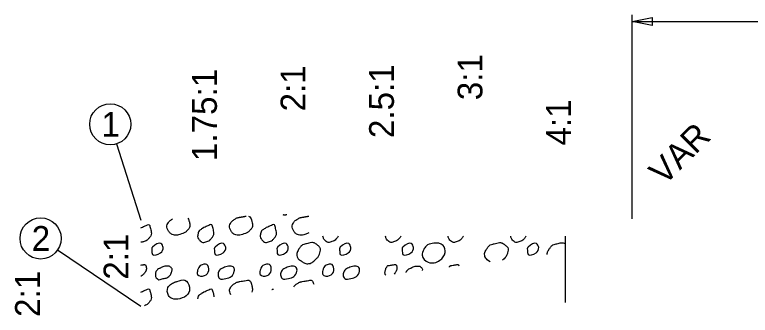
# Model space of a CAD drawing. Extents: x -1577 to 2037, y 0 to 220.
# Drawn here: x 62.87 to 104.42, y 151.65 to 168.62 of the extents above; entities that cross this region are included whole.
import ezdxf

# ---------------------------------------------------------------- set-up
doc = ezdxf.new("R2010")
doc.units = 0
for name, color, linetype in [('DR_P_Culvert', 7, 'Continuous'), ('GE_P_Alignment_100_Stations', 7, 'Continuous'), ('PF_X_Ground_Line', 7, 'Continuous'), ('XS_P_Pavt_Surface', 7, 'Continuous')]:
    doc.layers.add(name, color=color, linetype=linetype)

msp = doc.modelspace()

# ---------------------------------------------------------------- linework, layer by layer
at = {"layer": 'DR_P_Culvert'}
msp.add_line((93.987, 152.378), (93.987, 156.128), dxfattribs=at)
at = {"layer": 'GE_P_Alignment_100_Stations'}
for p, q in [((97.737, 157.091), (97.737, 168.619)), ((97.737, 168.239), (134.487, 168.239)), ((68.615, 161.328), (69.987, 157.031)), ((65.287, 155.341), (69.987, 152.167))]:
    msp.add_line(p, q, dxfattribs=at)
for centre in [(68.262, 162.432), (64.326, 155.99)]:
    msp.add_circle(centre, 1.16, dxfattribs=at)
at = {"layer": 'PF_X_Ground_Line'}
msp.add_lwpolyline([(98.866, 168.011), (97.737, 168.239), (98.866, 168.466)], close=True, dxfattribs=at)
msp.add_lwpolyline([(98.866, 168.011), (97.737, 168.239), (98.866, 168.466)], close=True, dxfattribs=at)
at = {"layer": 'XS_P_Pavt_Surface'}
for points, degree in [([(72.654, 157.128), (72.695, 157.049), (72.722, 156.949), (72.74, 156.879), (72.775, 156.75), (72.753, 156.593), (72.644, 156.473), (72.511, 156.325), (72.362, 156.268), (72.198, 156.22), (72.057, 156.178), (71.899, 156.163), (71.758, 156.223), (71.673, 156.259), (71.611, 156.321), (71.559, 156.401), (71.472, 156.535), (71.447, 156.719), (71.522, 156.846), (71.572, 156.93), (71.64, 157.004), (71.727, 157.059), (71.747, 157.072), (71.767, 157.085), (71.787, 157.097)], 3), ([(76.075, 157.253), (76.187, 157.211), (76.244, 157.002), (76.276, 156.879), (76.311, 156.75), (76.288, 156.593), (76.18, 156.473), (76.046, 156.325), (75.898, 156.268), (75.734, 156.22), (75.593, 156.178), (75.434, 156.163), (75.294, 156.223), (75.208, 156.259), (75.146, 156.321), (75.095, 156.401), (75.008, 156.535), (74.982, 156.719), (75.058, 156.846), (75.108, 156.93), (75.176, 157.004), (75.263, 157.059), (75.337, 157.106), (75.407, 157.15), (75.489, 157.168), (75.516, 157.173), (75.544, 157.179), (75.571, 157.185)], 3), ([(75.563, 157.183), (75.69, 157.205), (75.816, 157.229), (75.943, 157.248)], 2), ([(78.244, 157.332), (78.172, 157.312), (78.097, 157.293), (78.027, 157.324)], 2), ([(79.487, 156.3), (79.418, 156.266), (79.346, 156.242), (79.27, 156.22), (79.128, 156.178), (78.97, 156.163), (78.83, 156.223), (78.744, 156.259), (78.682, 156.321), (78.63, 156.401), (78.544, 156.535), (78.518, 156.719), (78.594, 156.846), (78.644, 156.93), (78.712, 157.004), (78.799, 157.059), (78.872, 157.106), (78.943, 157.15), (79.025, 157.168), (79.052, 157.173), (79.08, 157.179), (79.107, 157.185)], 3), ([(79.099, 157.183), (79.228, 157.206), (79.358, 157.23), (79.487, 157.25)], 2), ([(70.007, 156.601), (70.124, 156.651), (70.242, 156.701), (70.359, 156.752), (70.48, 156.804), (70.54, 156.537), (70.566, 156.413), (70.595, 156.282), (70.561, 156.135), (70.455, 156.008), (70.355, 155.889), (70.241, 155.832), (70.121, 155.796), (70.08, 155.783), (70.034, 155.775), (69.987, 155.778)], 3), ([(73.543, 156.601), (73.66, 156.651), (73.777, 156.701), (73.895, 156.752), (74.016, 156.804), (74.075, 156.537), (74.102, 156.413), (74.13, 156.282), (74.096, 156.135), (73.99, 156.008), (73.891, 155.889), (73.777, 155.832), (73.657, 155.796), (73.561, 155.767), (73.44, 155.762), (73.346, 155.855), (73.233, 155.967), (73.19, 156.1), (73.213, 156.214), (73.231, 156.305), (73.274, 156.425), (73.359, 156.482), (73.42, 156.522), (73.482, 156.561), (73.543, 156.601)], 3), ([(77.079, 156.601), (77.196, 156.651), (77.313, 156.701), (77.43, 156.752), (77.552, 156.804), (77.611, 156.537), (77.638, 156.413), (77.666, 156.282), (77.632, 156.135), (77.526, 156.008), (77.427, 155.889), (77.313, 155.832), (77.193, 155.796), (77.097, 155.767), (76.976, 155.762), (76.882, 155.855), (76.768, 155.967), (76.726, 156.1), (76.749, 156.214), (76.767, 156.305), (76.809, 156.425), (76.895, 156.482), (76.956, 156.522), (77.018, 156.561), (77.079, 156.601)], 3), ([(69.987, 156.588), (69.994, 156.592), (70, 156.597), (70.007, 156.601)], 2), ([(81.139, 156.128), (81.119, 156.087), (81.094, 156.047), (81.062, 156.008), (80.962, 155.889), (80.849, 155.832), (80.729, 155.796), (80.633, 155.767), (80.512, 155.762), (80.418, 155.855), (80.332, 155.94), (80.287, 156.036), (80.28, 156.128)], 3), ([(84.674, 156.128), (84.655, 156.087), (84.63, 156.047), (84.598, 156.008), (84.498, 155.889), (84.384, 155.832), (84.265, 155.796), (84.169, 155.767), (84.048, 155.762), (83.954, 155.855), (83.868, 155.94), (83.823, 156.036), (83.815, 156.128)], 3), ([(88.21, 156.128), (88.191, 156.087), (88.166, 156.047), (88.134, 156.008), (88.034, 155.889), (87.92, 155.832), (87.8, 155.796), (87.704, 155.767), (87.584, 155.762), (87.49, 155.855), (87.404, 155.94), (87.358, 156.036), (87.351, 156.128)], 3), ([(91.746, 156.128), (91.727, 156.087), (91.701, 156.047), (91.67, 156.008), (91.57, 155.889), (91.456, 155.832), (91.336, 155.796), (91.24, 155.767), (91.119, 155.762), (91.025, 155.855), (90.939, 155.94), (90.894, 156.036), (90.887, 156.128)], 3), ([(79.12, 155.632), (79.238, 155.663), (79.357, 155.694), (79.475, 155.725), (79.649, 155.77), (79.823, 155.738), (79.996, 155.593), (80.131, 155.481), (80.139, 155.315), (80.104, 155.191), (80.059, 155.034), (79.96, 154.886), (79.808, 154.756), (79.618, 154.594), (79.354, 154.53), (79.16, 154.645), (79.002, 154.738), (78.836, 154.878), (78.805, 155.043), (78.786, 155.146), (78.84, 155.266), (78.9, 155.362), (78.944, 155.43), (78.982, 155.499), (79.039, 155.554), (79.066, 155.58), (79.093, 155.606), (79.12, 155.632)], 3), ([(89.726, 154.671), (89.582, 154.763), (89.441, 154.893), (89.413, 155.043), (89.394, 155.146), (89.447, 155.266), (89.508, 155.362), (89.551, 155.43), (89.589, 155.499), (89.646, 155.554), (89.673, 155.58), (89.7, 155.606), (89.727, 155.632)], 3), ([(89.727, 155.632), (89.846, 155.663), (89.964, 155.694), (90.083, 155.725), (90.256, 155.77), (90.43, 155.738), (90.604, 155.593), (90.738, 155.481), (90.747, 155.315), (90.711, 155.191), (90.667, 155.035), (90.569, 154.888), (90.418, 154.758)], 3), ([(92.945, 155.079), (92.942, 155.173), (92.99, 155.277), (93.044, 155.362), (93.087, 155.43), (93.125, 155.499), (93.182, 155.554), (93.209, 155.58), (93.236, 155.606), (93.263, 155.632)], 3), ([(93.263, 155.632), (93.381, 155.663), (93.5, 155.694), (93.619, 155.725), (93.741, 155.757), (93.864, 155.75), (93.987, 155.692)], 3), ([(70.94, 154.242), (71.024, 154.284), (71.107, 154.325), (71.19, 154.367), (71.282, 154.413), (71.392, 154.422), (71.491, 154.425), (71.565, 154.427), (71.636, 154.409), (71.702, 154.344), (71.763, 154.284), (71.754, 154.204), (71.736, 154.14), (71.707, 154.035), (71.668, 153.929), (71.565, 153.844), (71.465, 153.761), (71.36, 153.749), (71.252, 153.724), (71.139, 153.697), (71.011, 153.631), (70.9, 153.73), (70.828, 153.795), (70.813, 153.871), (70.815, 153.945), (70.816, 154.012), (70.825, 154.09), (70.866, 154.145), (70.891, 154.178), (70.916, 154.21), (70.94, 154.242)], 3), ([(83.822, 153.922), (83.816, 153.93), (83.81, 153.939), (83.805, 153.949), (83.767, 154.026), (83.786, 154.117), (83.808, 154.195), (83.823, 154.25), (83.83, 154.312), (83.866, 154.358), (83.893, 154.392), (83.92, 154.425), (83.946, 154.459)], 3), ([(83.946, 154.459), (84.074, 154.477), (84.201, 154.497), (84.328, 154.515), (84.442, 154.53), (84.468, 154.285), (84.432, 154.186), (84.406, 154.115), (84.355, 154.044), (84.294, 153.982)], 3), ([(84.973, 154.068), (84.981, 154.096), (84.992, 154.123), (85.01, 154.145), (85.034, 154.178), (85.059, 154.21), (85.084, 154.242)], 3), ([(85.084, 154.242), (85.167, 154.284), (85.25, 154.325), (85.334, 154.367), (85.425, 154.413), (85.535, 154.422), (85.635, 154.425), (85.708, 154.427), (85.779, 154.409), (85.845, 154.344), (85.893, 154.297), (85.898, 154.238), (85.889, 154.184)], 3), ([(87.418, 154.378), (87.439, 154.405), (87.461, 154.432), (87.482, 154.459)], 2), ([(87.482, 154.459), (87.609, 154.477), (87.737, 154.497), (87.864, 154.515), (87.906, 154.52), (87.935, 154.491), (87.955, 154.446)], 3), ([(75.07, 152.812), (75.004, 152.941), (74.99, 153.102), (75.058, 153.215), (75.108, 153.299), (75.176, 153.373), (75.263, 153.429), (75.337, 153.476), (75.407, 153.52), (75.489, 153.537), (75.516, 153.543), (75.544, 153.549), (75.571, 153.555)], 3), ([(75.563, 153.553), (75.714, 153.579), (75.866, 153.608), (76.017, 153.629), (76.168, 153.65), (76.238, 153.391), (76.276, 153.249), (76.3, 153.16), (76.297, 153.057), (76.257, 152.963)], 3), ([(78.625, 153.263), (78.671, 153.327), (78.729, 153.384), (78.799, 153.429), (78.872, 153.476), (78.943, 153.52), (79.025, 153.537), (79.052, 153.543), (79.08, 153.549), (79.107, 153.555)], 3), ([(79.099, 153.553), (79.25, 153.579), (79.402, 153.608), (79.553, 153.629), (79.656, 153.643), (79.721, 153.527), (79.764, 153.407)], 3), ([(69.987, 152.957), (69.994, 152.962), (70, 152.966), (70.007, 152.97)], 2), ([(70.007, 152.97), (70.124, 153.021), (70.242, 153.071), (70.359, 153.121), (70.48, 153.173), (70.54, 152.907), (70.566, 152.783), (70.595, 152.652), (70.561, 152.505), (70.455, 152.378), (70.379, 152.287), (70.294, 152.232), (70.205, 152.195)], 3), ([(73.212, 152.576), (73.212, 152.579), (73.212, 152.581), (73.213, 152.584), (73.231, 152.675), (73.274, 152.795), (73.359, 152.851), (73.42, 152.892), (73.482, 152.93), (73.543, 152.97)], 3), ([(73.543, 152.97), (73.66, 153.021), (73.777, 153.071), (73.895, 153.121), (74.016, 153.173), (74.075, 152.907), (74.102, 152.783), (74.109, 152.753), (74.112, 152.722), (74.112, 152.691)], 3), ([(77.398, 153.107), (77.409, 153.112), (77.42, 153.117), (77.43, 153.121), (77.454, 153.131), (77.475, 153.129), (77.494, 153.119)], 3)]:
    msp.add_open_spline(points, degree=degree, dxfattribs=at)
for points in [[(70.649, 155.506), (71.124, 155.698), (71.25, 155.48), (71.1, 155.178), (70.65, 155.093), (70.611, 155.333), (70.615, 155.454), (70.649, 155.506)], [(74.185, 155.506), (74.66, 155.698), (74.785, 155.48), (74.636, 155.178), (74.186, 155.093), (74.147, 155.333), (74.151, 155.454), (74.185, 155.506)], [(77.72, 155.506), (78.195, 155.698), (78.321, 155.48), (78.172, 155.178), (77.722, 155.093), (77.683, 155.333), (77.687, 155.454), (77.72, 155.506)], [(81.256, 155.506), (81.731, 155.698), (81.857, 155.48), (81.708, 155.178), (81.258, 155.093), (81.219, 155.333), (81.223, 155.454), (81.256, 155.506)], [(84.792, 155.506), (85.267, 155.698), (85.393, 155.48), (85.244, 155.178), (84.794, 155.093), (84.755, 155.333), (84.759, 155.454), (84.792, 155.506)], [(86.191, 155.632), (86.547, 155.725), (87.068, 155.593), (87.175, 155.191), (86.88, 154.756), (86.231, 154.645), (85.877, 155.043), (85.972, 155.362), (86.11, 155.554), (86.191, 155.632)], [(91.864, 155.506), (92.339, 155.698), (92.465, 155.48), (92.315, 155.178), (91.865, 155.093), (91.826, 155.333), (91.83, 155.454), (91.864, 155.506)], [(73.339, 154.459), (73.72, 154.515), (73.825, 154.186), (73.585, 153.892), (73.198, 153.949), (73.2, 154.195), (73.259, 154.358), (73.339, 154.459)], [(76.875, 154.459), (77.256, 154.515), (77.36, 154.186), (77.12, 153.892), (76.734, 153.949), (76.736, 154.195), (76.795, 154.358), (76.875, 154.459)], [(80.41, 154.459), (80.792, 154.515), (80.896, 154.186), (80.656, 153.892), (80.27, 153.949), (80.272, 154.195), (80.33, 154.358), (80.41, 154.459)], [(69.987, 154.486), (69.994, 154.487), (70.089, 154.501), (70.137, 154.508), (70.161, 154.511), (70.185, 154.515), (70.195, 154.515), (70.205, 154.514), (70.214, 154.512), (70.219, 154.511), (70.223, 154.509), (70.232, 154.504), (70.24, 154.498), (70.247, 154.492), (70.251, 154.488), (70.254, 154.484), (70.268, 154.462), (70.279, 154.44), (70.287, 154.417), (70.293, 154.393), (70.301, 154.337), (70.304, 154.309), (70.304, 154.281), (70.302, 154.255), (70.299, 154.229), (70.295, 154.206), (70.292, 154.196), (70.289, 154.186), (70.271, 154.146), (70.249, 154.105), (70.192, 154.028), (70.176, 154.009), (70.159, 153.991), (70.142, 153.973), (70.124, 153.956), (70.087, 153.923), (70.068, 153.907), (70.058, 153.899), (70.049, 153.892), (70.035, 153.882), (70.027, 153.878), (70.02, 153.874), (69.987, 153.859)], [(74.476, 154.242), (74.726, 154.367), (75.027, 154.425), (75.238, 154.344), (75.272, 154.14), (75.101, 153.844), (74.788, 153.724), (74.436, 153.73), (74.35, 153.945), (74.402, 154.145), (74.476, 154.242)], [(78.012, 154.242), (78.262, 154.367), (78.563, 154.425), (78.774, 154.344), (78.808, 154.14), (78.637, 153.844), (78.324, 153.724), (77.972, 153.73), (77.886, 153.945), (77.938, 154.145), (78.012, 154.242)], [(81.548, 154.242), (81.798, 154.367), (82.099, 154.425), (82.31, 154.344), (82.344, 154.14), (82.173, 153.844), (81.86, 153.724), (81.508, 153.73), (81.422, 153.945), (81.474, 154.145), (81.548, 154.242)], [(72.027, 153.553), (72.481, 153.629), (72.74, 153.249), (72.644, 152.842), (72.198, 152.59), (71.758, 152.592), (71.559, 152.77), (71.522, 153.215), (71.727, 153.429), (71.953, 153.537), (72.035, 153.555)]]:
    msp.add_spline(points, degree=3, dxfattribs=at)

# ---------------------------------------------------------------- texts
at = {"layer": 'GE_P_Alignment_100_Stations'}
for s, rotation, p in [('3:1', 90, (89.287, 163.793)), ('1.75:1', 90, (74.287, 160.359)), ('2:1', 90, (79.287, 163.16)), ('2.5:1', 90, (84.287, 161.656)), ('4:1', 90, (94.287, 161.238)), ('VAR', 44.9625, (99.554, 158.933)), ('2:1', 90, (69.287, 153.66)), ('2:1', 90, (64.287, 151.56))]:
    msp.add_text(s, height=1.4, rotation=rotation, dxfattribs=at).set_placement(p)
for s, p in [('1', (67.763, 161.732)), ('2', (63.828, 155.29))]:
    msp.add_text(s, height=1.4, dxfattribs=at).set_placement(p)

doc.saveas('drawing.dxf')
